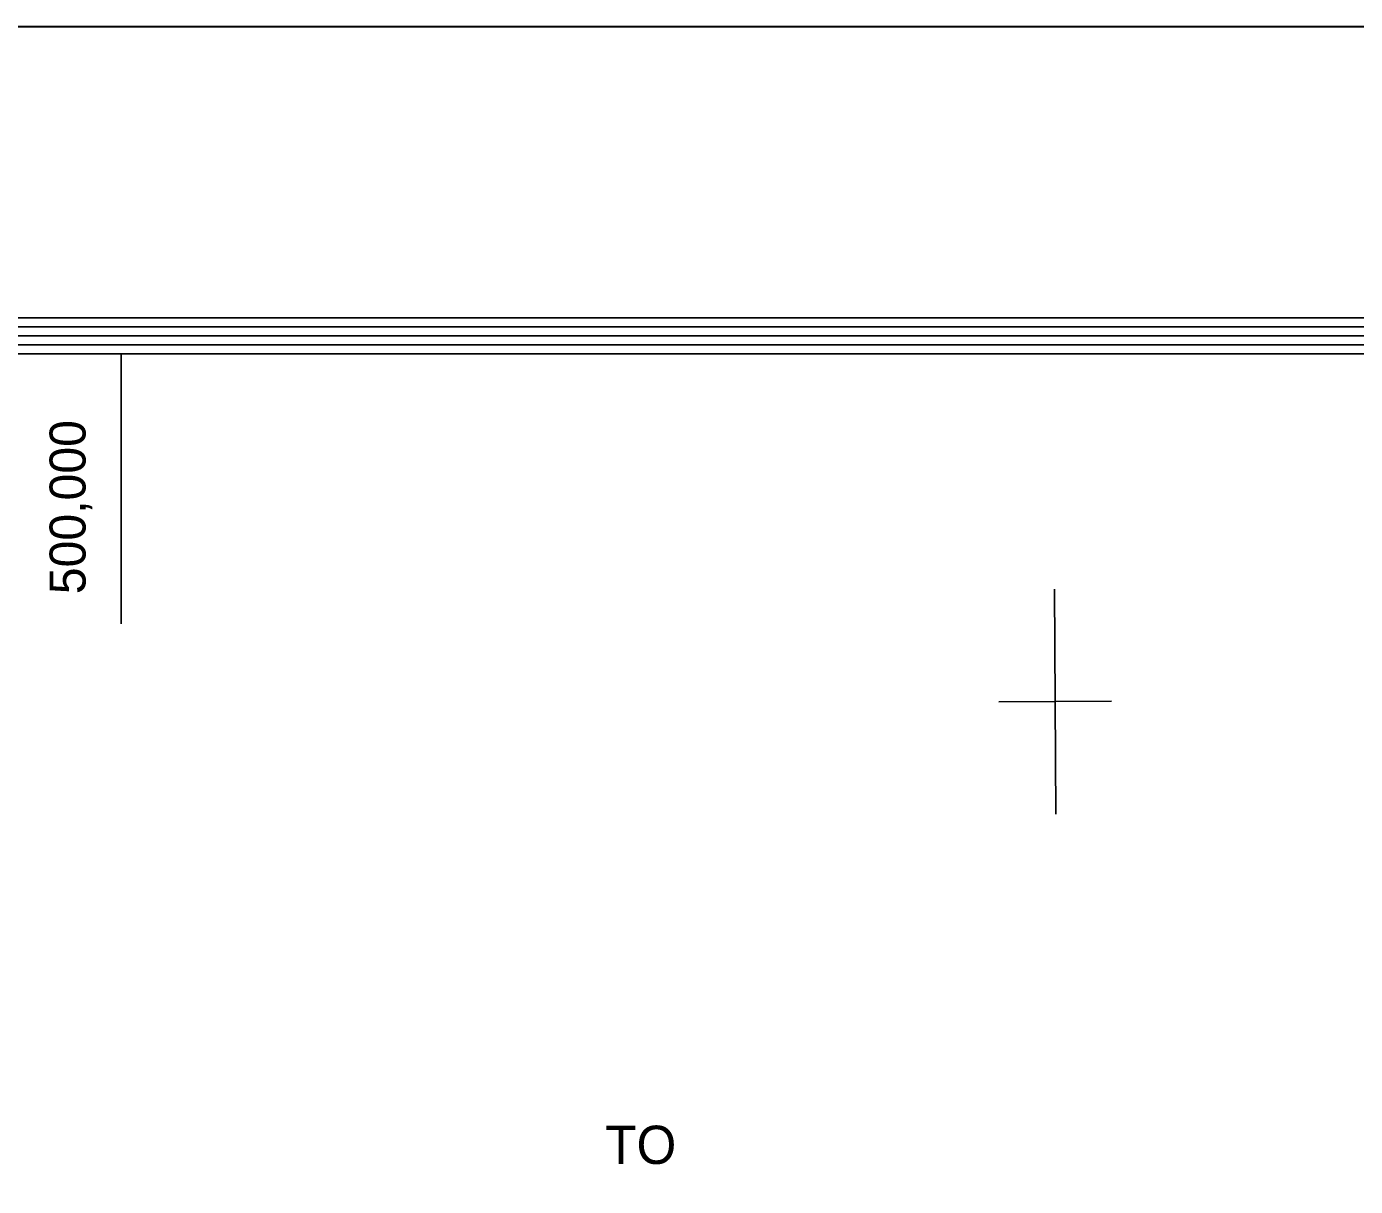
# Model space of a CAD drawing. Extents: x 380424 to 701066, y 1117407 to 1412949.
# Drawn here: x 499000 to 513759, y 1400070 to 1412949 of the extents above; entities that cross this region are included whole.
import ezdxf

# ---------------------------------------------------------------- set-up
doc = ezdxf.new("R2010")
doc.units = 0
for name, color, linetype in [('Cities Incorporated Area', 7, 'Continuous'), ('Coordinate ticks State Plane', 7, 'Continuous'), ('Cut Border', 7, 'Continuous'), ('Interstates Related Text', 7, 'Continuous'), ('Map Border', 7, 'Continuous'), ('Map Border Text and Cells', 7, 'Continuous'), ('Township  and Range Tics', 7, 'Continuous'), ('US Highways Related Text', 7, 'Continuous')]:
    doc.layers.add(name, color=color, linetype=linetype)

msp = doc.modelspace()

# ---------------------------------------------------------------- linework, layer by layer
at = {"layer": 'Cities Incorporated Area'}
msp.add_lwpolyline([(380435, 1412948), (380424, 1117408), (701065, 1117408), (701065, 1412948)], close=True, dxfattribs=at)
at = {"layer": 'Coordinate ticks State Plane'}
msp.add_line((500049, 1406316), (500049, 1409316), dxfattribs=at)
at = {"layer": 'Cut Border'}
msp.add_lwpolyline([(380424, 1117407), (380424, 1412948), (701066, 1412949), (701065, 1117408)], close=True, dxfattribs=at)
at = {"layer": 'Interstates Related Text'}
msp.add_lwpolyline([(380424, 1412948), (701065, 1412948), (701065, 1117408), (380424, 1117408)], close=True, dxfattribs=at)
at = {"layer": 'Map Border'}
for points in [[(697834, 1409717), (390784, 1409716), (390784, 1120639), (697833, 1120640)], [(697734, 1409617), (390884, 1409616), (390884, 1120739), (697733, 1120740)], [(697634, 1409517), (390984, 1409516), (390984, 1120839), (697633, 1120840)], [(697534, 1409417), (391084, 1409416), (391084, 1120939), (697533, 1120940)], [(697434, 1409317), (391184, 1409316), (391184, 1121039), (697433, 1121040)]]:
    msp.add_lwpolyline(points, close=True, dxfattribs=at)
at = {"layer": 'Township  and Range Tics'}
for p, q in [((510418, 1406703), (510432, 1404203)), ((509800, 1405450), (511050, 1405457))]:
    msp.add_line(p, q, dxfattribs=at)

# ---------------------------------------------------------------- texts
at = {"layer": 'Map Border Text and Cells'}
msp.add_text('500,000 ', height=400, rotation=90.0001, dxfattribs=at).set_placement((499655, 1406646))
at = {"layer": 'US Highways Related Text'}
msp.add_text('TO', height=425, rotation=359.9996, dxfattribs=at).set_placement((505427, 1400319))

doc.saveas('drawing.dxf')
